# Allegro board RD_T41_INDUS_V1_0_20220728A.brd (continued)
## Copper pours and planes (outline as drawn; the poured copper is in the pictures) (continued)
VCC_SYS on BOTTOM: 99.44,39.58 99.44,42.71 99.59,42.86 100.16,42.86 100.4,43.11 100.4,64.94 99.05,66.29 98.16,66.29 97.86,66.6 97.86,67.51 97.96,67.61 98.61,67.61 99.53,68.54 99.53,79.98 95.35,84.16 74.66,84.16 68.46,77.97 42.01,77.97 37.67,73.63 37.67,73.61 30.74,66.68 14.29,66.68 13.26,65.65 13.26,63.82 11.16,61.73 11.16,58.04 10.7,57.58 8.59,57.58 8.13,58.04 8.13,62.44 9.25,63.56 9.82,63.56 11.38,65.12 11.38,67.27 13.29,69.18 27.43,69.18 31.73,73.48 40.89,82.64 67.08,82.64 71.35,86.91 96.4,86.91 101.78,81.53 101.78,41.93 101.09,41.23 101.09,39.62 100.88,39.41 99.61,39.41
VCCQ_3V3 on TOP: 62.09,9.99 61.34,9.99 59.77,8.42 59.77,4.16 61.27,2.66 68.01,2.66 68.26,2.92 68.26,3.34 68.02,3.58 62.71,3.58 62.7,3.6 62.3,3.6 61.85,4.05 61.85,7.81 62.34,8.3 62.34,9.74
VCCQ_3V3 on BOTTOM: 60.39,8.64 59.66,8.64 59.44,8.42 59.44,7.41 59.62,7.23 60.42,7.23 60.57,7.39 60.57,8.46
VDDMSC0 on BOTTOM: 46.83,16.42 46.65,16.24 46.65,11.14 47,10.78 47.64,10.78 48.07,11.21 48.07,13.47 47.89,13.65 47.89,16.32 47.79,16.42
DDRVDD on TOP: 58.34,32.27 57.37,32.27 57.18,32.46 57.18,37.2 57.34,37.36 57.6,37.36 57.97,36.99 58.49,36.99 58.5,36.99 58.5,32.43
DDRVDD on BOTTOM: 57.93,37.75 57.6,37.75 57.42,37.57 57.42,36.6 57.62,36.4 57.62,35.94 57.4,35.71 57.4,35.26 57.62,35.03 57.62,34.57 57.4,34.34 57.4,34.06 57.65,33.81 57.65,33.3 57.4,33.05 57.4,32.62 57.73,32.29 57.73,31.63 57.76,31.59 57.76,29.78 58.87,28.67 58.89,28.67 59.07,28.49 69.28,28.49 70.25,29.46 70.25,31.84 70.01,32.08 68.91,32.08 68.68,31.86 68.68,31.08 68.21,30.61 59.82,30.61 59.35,31.08 59.35,33.87 59.2,34.02 59.2,34.98 59.35,35.13 59.35,37.57 59.21,37.71 58.68,37.71 58.59,37.62 58.59,37.19 58.49,37.09 58.11,37.09 58.01,37.19 58.01,37.67
DDRVDD on L3_PWR: 58.76,37.09 57.42,37.09 57.33,36.99 57.33,32.77 61.06,29.04 66.51,29.04 66.84,29.37 66.84,30.51 66.27,31.08 62.39,31.08 59.22,34.25 59.22,36.63
DVP_3V3 on TOP: 36.24,75.6 36.24,69.7 36.44,69.5 37.28,69.5 37.31,69.53 37.31,73.67 37.76,74.11 37.76,75.56 37.63,75.69 36.33,75.69
DVP_5V on TOP: 53.69,73.26 53.2,73.75 53.2,75.66 53.43,75.89 54.66,75.89 54.98,75.56 54.98,72.73 55.6,72.12 57.89,72.12 58.68,71.33 58.68,70.53 58.33,70.18 54.53,70.18 53.69,71.02
MCU_PWR on TOP: 88.98,47.24 86.18,47.24 85.94,47 85.94,45.51 86.11,45.34 89.05,45.34 89.24,45.52 89.24,46.98
MCU_PWR on BOTTOM: 87.5,47.3 86.28,47.3 86.03,47.05 86.03,45.01 86.32,44.72 87.52,44.72 87.64,44.83 87.64,47.16
MIPI1_2LANE_3V3 on TOP: 40.38,54.91 40.38,59.16 39.64,59.9 39.64,60.75 39.8,60.91 40.54,60.91 40.73,60.73 40.73,60.19 41.18,59.73 41.18,56.78 41.74,56.21 41.74,54.88 41.56,54.7 40.59,54.7
MIPI1_2LANE_5V on TOP: 42.16,60.77 41.59,60.77 41.47,60.65 41.47,56.72 41.92,56.27 41.92,54.65 42.04,54.54 42.63,54.54 42.71,54.62 42.71,56.51 42.28,56.94 42.28,60.65
PIR_3V3 on BOTTOM: 83.26,80.31 84.62,80.31 84.62,80.31 84.77,80.31 84.91,80.46 84.91,81.65 84.71,81.86 83.33,81.86 83.21,81.73 83.21,80.37
PIR_3V3 on BOTTOM: 93.54,80.9 97.18,80.9 97.79,80.28 97.79,73.99 97.44,73.65 96.81,73.65 96.63,73.83 96.63,77.4 94.5,79.53 93.56,79.53 93.38,79.71 93.38,80.73
SLCD_LEDK on TOP: 98.13,20.77 97.35,20.77 97.28,20.7 97.28,18.92 97.42,18.78 98.02,18.78 98.22,18.97 98.22,20.68
SLCD_LEDK on BOTTOM: 98.09,21.85 99.26,21.85 100.01,22.6 100.01,23.31 100.09,23.39 100.77,23.39 100.85,23.3 100.85,21.72 97.99,18.86 97.41,18.86 97.27,19 97.27,20.21 97.96,20.9 97.96,21.72
SOC_0V8 on TOP: 52.82,33.37 52.62,33.37 52.52,33.27 52.21,33.27 52.1,33.39 52.1,36.48 53.32,37.7 56.02,37.7 56.38,37.34 56.38,36.37 56.51,36.25 56.51,36.05 56.36,35.91 56.36,35.1 56.51,34.96 56.51,34.73 56.36,34.59 56.36,33.79 56.51,33.64 56.51,33.48 56.36,33.33 56.36,32.45 56.51,32.3 56.51,32.16 56.34,31.99 56.34,31.72 56.51,31.56 56.51,31.11 56.33,30.94 55.85,30.94 55.27,31.52 54.5,31.52 54.42,31.59 54.42,32.06 54.75,32.39 55.51,32.39 55.66,32.55 55.66,36.44 55.66,36.56 55.44,36.77 53.73,36.77 52.93,35.97 52.93,33.48
SOC_0V8 on BOTTOM: 51.99,33.56 51.99,34.37 51.86,34.5 48.61,34.5 48.43,34.67 48.43,35.38 48.48,35.44 48.49,35.44 48.6,35.55 50.35,35.55 50.56,35.75 50.56,36.19 50.66,36.29 51.06,36.29 51.08,36.3 51.84,36.3 53.33,37.79 53.33,38.1 53.47,38.24 55.88,38.24 56.27,37.86 56.27,37.09 56.53,36.82 56.53,27.95 57.27,27.21 66.25,27.21 66.51,26.96 66.51,25 66.4,24.88 63.7,24.88 63.69,24.88 59.31,24.88 58.59,24.16 57.62,24.16 55.24,26.53 55.24,30 55.33,30.09 55.33,31.01 55.04,31.29 54.81,31.29 54.4,31.7 54.2,31.7 54.14,31.75 54.14,32.23 54.37,32.46 55.29,32.46 55.52,32.69 55.52,36.96 55.26,37.21 53.92,37.21 52.98,36.27 52.98,33.58 52.7,33.3 52.24,33.3
SOC_0V8 on L3_PWR: 58.82,23.45 54.92,23.45 49.64,28.74 49.64,35.79 52.08,38.24 56.21,38.24 56.62,37.83 56.62,31.43 56.62,31.43 56.62,30.93 59.46,28.1 59.46,24.09
SOC_1V8 on TOP: 45.81,41.92 45.81,41.54 45.73,41.46 45.45,41.46 45.44,41.47 44,41.47 43.56,41.91 35.25,41.91 34.69,42.48 34.69,43.06 34.81,43.18 35.37,43.18 35.37,43.18 39.42,43.18 39.74,42.85 44.88,42.85
SOC_1V8 on BOTTOM: 44.94,42.02 45.78,42.02 45.9,41.89 45.9,41.35 45.75,41.2 44.74,41.2 44.65,41.29 44.65,41.72
SOC_1V8 on BOTTOM: 35.08,41.46 33.48,41.46 33.29,41.65 33.29,42.48 33.58,42.77 34.33,42.77 34.69,43.12 35.17,43.12 35.35,42.94 35.35,41.73
SOC_1V8 on BOTTOM: 50.72,43.29 52.13,43.29 52.27,43.42 52.27,44.13 51.99,44.41 50.72,44.41 50.59,44.27 50.59,43.42
SOC_3V3 on TOP: 38.9,39.3 43.46,39.3 44.19,40.03 45.24,40.03 45.43,40.22 45.43,40.63 45.17,40.89 43.42,40.89 42.75,40.23 38.68,40.23 38.68,40.22 37.75,40.22 37.64,40.11 37.64,39.54 37.89,39.3 38.89,39.3
SOC_3V3 on BOTTOM: 38.79,45.46 38.79,39.64 38.6,39.46 37.68,39.46 37.06,40.08 37.06,45.3 33.61,48.75 33.61,49.93 33.85,50.16 35.08,50.16 35.61,49.63 35.61,48.63
WIFI_IO on TOP: 90.2,47.13 92.93,47.13 93.68,47.88 94.81,47.88 94.99,47.7 94.99,46.49 94.67,46.18 90.09,46.18 90.02,46.24 90.02,46.95
WIFI_VBAT on TOP: 71.13,62.57 85.57,62.57 85.88,62.27 85.88,61.2 85.61,60.93 77.93,60.93 77.49,60.49 71.18,60.49 71.01,60.67 71.01,62.45
WIFI_VBAT on BOTTOM: 83.42,40.58 83.42,40.58 83.42,40.11 85.09,38.43 87.86,38.43 88.17,38.75 88.17,39.53 87.98,39.72 85.77,39.72 85,40.49 85,60.34 85.68,61.02 85.68,62.26 85.36,62.58 83.67,62.58 83.42,62.33
N6875993 on TOP: 10.13,87.89 9.45,87.89 9.1,87.54 9.1,83.19 9.39,82.9 9.55,82.9 9.62,82.97 9.62,82.98 9.66,83.02 9.66,84.81 9.89,85.04 9.89,85.98 10.18,86.27 10.18,87.84
N6876005 on TOP: 11.49,87.89 10.92,87.89 10.76,87.73 10.76,86.33 10.96,86.14 10.96,85.12 11.27,84.81 11.27,83.07 11.39,82.95 11.79,82.95 11.98,83.13 11.98,85.05 11.69,85.34 11.69,87.69
N16605539 on BOTTOM: 16.94,47.06 14.93,47.06 14.73,46.86 14.73,45.3 14.92,45.11 16.94,45.11 17.06,45.23 17.06,46.94
N16607200 on BOTTOM: 5.99,62.49 3.89,62.49 3.68,62.29 3.68,57.88 3.99,57.58 6.11,57.58 6.53,58 6.53,61.95
N16626314 on BOTTOM: 96.04,43.99 97.03,43.99 97.53,44.48 100.12,44.48 100.19,44.41 100.19,43.61 100.09,43.51 96.97,43.51 96.8,43.68 96.02,43.68 96.02,43.67 95.96,43.73 95.96,43.91
N16626534 on BOTTOM: 76.16,33.67 71.09,33.67 70.76,33.34 70.76,31.23 70.78,31.22 71.89,31.22 72.12,31.44 74.14,31.44 74.4,31.7 76.48,31.7 76.57,31.62 78.05,31.62 78.1,31.67 78.1,32.14 77.71,32.53 77.29,32.53
N16626718 on BOTTOM: 78.03,30.88 76.55,30.88 76.4,30.73 74.68,30.73 74.52,30.57 74.52,29.76 74.75,29.53 76.67,29.53 77.08,29.94 77.9,29.94 78.08,30.12 78.08,30.83
N16626738 on BOTTOM: 30.07,52.44 27.32,52.44 27.04,52.15 27.04,51.46 27.11,51.39 27.64,51.39 27.65,51.38 28.13,51.38 28.3,51.55 30.03,51.55 30.15,51.67 30.15,52.35
N16627266 on BOTTOM: 94.47,43.29 92.79,43.29 92.56,43.06 92.56,40.91 92.78,40.69 93.53,40.69 94.05,41.2 94.05,42.1 94.56,42.61 94.56,43.2
N16676932 on BOTTOM: 30.6,45.9 28.9,45.9 28.61,45.6 27.55,45.6 27.47,45.52 27.47,44.85 27.54,44.79 28.9,44.79 29.05,44.94 30.62,44.94 30.7,45.03 30.7,45.8
N17002587 on TOP (solid shape): 21.87,20.26 21.87,7.27 21.53,6.93 18.98,6.93 18.72,7.19 18.72,12.1 19.51,12.89 19.51,14.46 19.09,14.88 17.61,14.88 17.5,14.99 17.5,15.3 17.54,15.34 19.01,15.34 19.45,15.79 19.45,17.28 19.33,17.41 17.55,17.41 17.47,17.49 17.47,17.9 17.51,17.94 19.25,17.94 19.42,18.1 19.42,20.81 19.01,21.22 17.5,21.22 17.44,21.28 17.44,21.64 17.53,21.73 20.41,21.73
N17002738 on TOP (solid shape): 25.14,10.69 25.14,7.79 24.72,7.37 23.21,7.37 22.63,7.94 22.63,10.71 22.8,10.88 24.95,10.88
N17009089 on BOTTOM: 97.55,72.22 96.82,72.22 96.73,72.13 96.73,68.7 97.06,68.37 98.47,68.37 98.62,68.52 98.62,69.42 98.41,69.63 97.98,69.63 97.76,69.85 97.76,72
N17009885 on BOTTOM: 80.68,81.75 73.12,81.75 72.43,81.06 72.43,80.11 72.62,79.92 73.74,79.92 74.18,80.36 80.76,80.36 80.86,80.46 80.86,81.57
N17009958 on BOTTOM: 80.26,79.81 83.89,79.81 83.96,79.73 83.96,79.07 83.85,78.96 80.47,78.96 80.22,79.22 80.22,79.73 80.2,79.75
N17141452 on BOTTOM: 16.73,65.36 16.73,64.36 16.44,64.07 14.13,64.07 13.89,64.31 13.89,65.44 14.16,65.71 16.38,65.71
N17219479 on BOTTOM: 29.73,78.3 26.32,78.3 25.72,77.7 25.72,75.51 25.87,75.35 27.08,75.35 27.77,76.04 29.87,76.04 29.99,76.16 29.99,78.04
N17219520 on L3_PWR: 27.32,60.38 25.75,60.38 25.15,60.97 25.15,68.35 23.03,70.47 23.03,76.75 23.38,77.1 24.41,77.1 24.98,76.53 24.98,74.98 28.42,71.54 28.42,61.48
N17219530 on TOP: 23.43,60.29 24.15,60.29 24.49,60.63 24.49,61.51 21.59,64.41 21.31,64.41 20.42,63.52 20.42,63.3
N17242896 on BOTTOM: 67.28,25.02 67.39,24.91 70.92,24.91 71.08,25.07 72.81,25.07 72.81,25.07 72.94,25.07 73.23,24.78 73.69,24.78 73.85,24.94 74.46,24.94 74.5,24.98 74.5,25.38 74.3,25.58 73.6,25.58 73.01,26.18 73.01,26.49 72.43,27.07 67.76,27.07 67.28,26.59
N17242946 on BOTTOM: 73.03,24.11 71.17,24.11 71.08,24.01 71.08,22.68 71.12,22.63 73.16,22.63 73.51,22.98 74.36,22.98 74.5,23.12 74.5,24.12 74.44,24.18 73.1,24.18
N17251042 on BOTTOM: 99.53,38.09 99.53,38.79 99.58,38.85 100.77,38.85 100.92,38.7 100.92,36.76 100.69,36.53 98.93,36.53 98.54,36.92 97.95,36.92 97.9,36.97 97.9,37.18 97.94,37.21 98.65,37.21
N17251195 on BOTTOM: 96.45,36.56 95.42,36.56 95.14,36.28 93.29,36.28 93.16,36.15 93.16,35.45 93.44,35.17 96.19,35.17 96.5,35.48 96.5,36.51

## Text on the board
BOTTOM: Artwork L4_BOT
Package Geometry/Pastemask Bottom: Artwork Paste_bot
Ref Des/Silkscreen Bottom: VCC_SOC | 3V3 | 1V8 | TEST_TE | SOC_0V8 | DDRVDD | EMMC_DS | WIFI_VBAT | VCC_3V3 | PIR_3V3 | TRST | Artwork Silk_bot
User.Comments: CR_DCDC_2 | Artwork Solder_top | Artwork Solder_bot
TOP: Artwork L1_TOP
Package Geometry/Pastemask Top: Artwork Paste_top
Ref Des/Silkscreen Top: RJ45 | VCC_5V | PWR_ON | K | SPK | NTC | MIC | MCLK | MIPI_MCLK | RTC_0V8 | RTC_1V8 | OFF | BT | ON | SD_CARD | HSYNC | VSYNC | PWDN | SCK | SDA | DATAN1_D2 | RESET | DATAP1_D3 | PWRON | CKN_D4 | CKP_D5 | RST_OUT | DATAP0_D1 | DATAN0_D0 | WKUP | DVP_MCLK | DVP_PCK | BT656 | DEBUG | KEY1_PB30 | KEY_IOT_N | BOOTSEL0 | Artwork Silk_top
L2_GND: Artwork L2_GND
L3_PWR: Artwork L3_PWR
DIMENSION: will.liu | will.qyliu | 15005694403 | Artwork drill_drawing | RD_T41_INDUS | XX_XX_XXXXX | 1.0 | XX | XXXXX | XXXX-XX-XX | 2022-07-28
User.14: FIGURE | SIZE | 8.0 | 15.7 | 19.7 | 23.6 | 25.2 | 35.0 | 35.4 | 60.0 | 70.1 | 126.0 | 39.4 | 127.9 | 47.2x19.7 | 118.1x78.7 | DRILL CHART: TOP to BOTTOM | ALL UNITS ARE IN MILS | PLATED | NON-PLATED | QTY | 1508 | 32 | 2 | 34 | 3 | 10 | 11 | 1 | 13 | 4
